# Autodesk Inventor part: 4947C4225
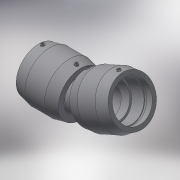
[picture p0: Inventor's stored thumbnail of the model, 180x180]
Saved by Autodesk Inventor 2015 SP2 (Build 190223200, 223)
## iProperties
Created: 2017-06
Part Number: 4947C4225
Material: Generic
Description: PLASSON ADJUSTABLE ELBOW 225
Document SubType Name: Modeling
Designer: KIM
Mass: 13468.6 g
Surface Area: 10357.8 cm^2
Volume: 13468.6 cm^3
Density: 1 g/cm^3
Appearance: Default
Author: KIM
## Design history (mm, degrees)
derived "4947C4.ipt"
feature "Solid1::4947C4.ipt"
tag "TaggingFeature1"
body "Solid1"
other parameters: "d2" = 282, "d3" = 105, "d4" = 52.5, "d5" = 253.8, "d7" = 225, "d8" = 168 deg, "d10" = 42, "d11" = 14, "d29" = 141, "d30" = 15, "d31" = 96, "d34" = 5 deg, "d41" = 4, "d42" = 14, "d43" = 0, "d48" = 202.5, "d49" = 24 deg, "d51" = 78 deg, "d52" = 90 deg, "d55" = 67.5, "d57" = 168 deg, "d58" = 13.5, "d60" = 75.56196, "d62" = 3, "d63" = 0, "d_" = 225, "L_1" = 105, "D_" = 282, "A_" = 141, "d_2" = 12, "L_0" = 148, "d54" = 135, "d59" = 251.87321
